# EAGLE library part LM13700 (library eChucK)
LM13700 Variable Gain Amplifier
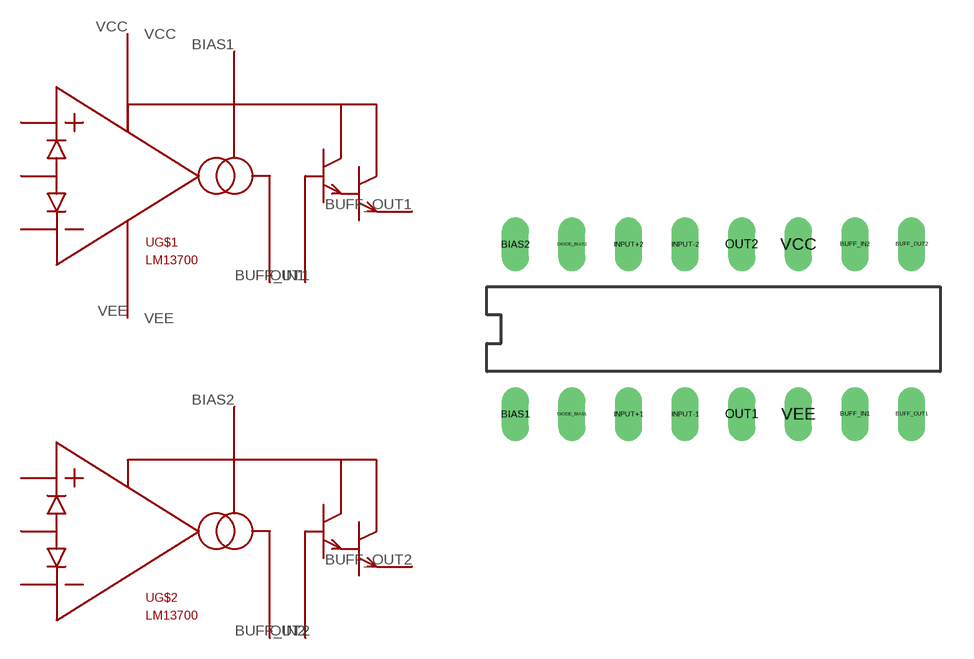
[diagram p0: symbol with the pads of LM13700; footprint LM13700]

Designator prefix U; gates G$1=LM13700 G$2=LM13700 G$3=LM13700_PWR

## LM13700  [LM13700]
BIAS1  G$1:BIAS
BIAS2  G$2:BIAS
BUFF_IN1  G$1:BUFF_IN
BUFF_IN2  G$2:BUFF_IN
BUFF_OUT1  G$1:BUFF_OUT
BUFF_OUT2  G$2:BUFF_OUT
DIODE_BIAS1  G$1:DIODE_BIAS
DIODE_BIAS2  G$2:DIODE_BIAS
INPUT+1  G$1:INPUT+
INPUT+2  G$2:INPUT+
INPUT-1  G$1:INPUT-
INPUT-2  G$2:INPUT-
OUT1  G$1:OUT
OUT2  G$2:OUT
VCC  G$3:VCC
VEE  G$3:VEE

## Footprint LM13700 (pad centres in mm)
drill 0.7 long: BIAS1 -8.89,-3.81; BIAS2 -8.89,3.81; BUFF_IN1 6.35,-3.81; BUFF_IN2 6.35,3.81; BUFF_OUT1 8.89,-3.81; BUFF_OUT2 8.89,3.81; DIODE_BIAS1 -6.35,-3.81; DIODE_BIAS2 -6.35,3.81; INPUT+1 -3.81,-3.81; INPUT+2 -3.81,3.81; INPUT-1 -1.27,-3.81; INPUT-2 -1.27,3.81; OUT1 1.27,-3.81; OUT2 1.27,3.81; VCC 3.81,3.81; VEE 3.81,-3.81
